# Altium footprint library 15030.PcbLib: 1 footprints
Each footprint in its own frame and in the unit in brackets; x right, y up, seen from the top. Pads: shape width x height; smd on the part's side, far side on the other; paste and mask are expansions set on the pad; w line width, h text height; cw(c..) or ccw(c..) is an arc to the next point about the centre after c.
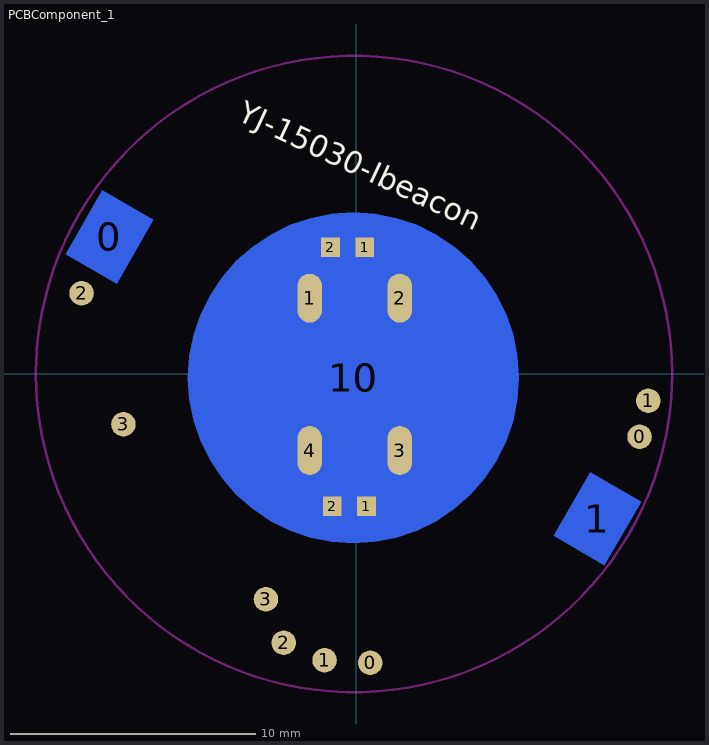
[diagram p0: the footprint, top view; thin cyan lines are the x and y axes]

## PCBComponent_1 [mm]
pads (19):
  rect 2.4x3 smd far side rot 150: 0(-10.074,5.58) 1(9.836,-5.915)
  round 1 smd: 0(0.563,-11.798) 0(11.558,-2.568) 1(-1.297,-11.688) 1(11.917,-1.107) 2(-11.214,3.286) 2(-2.967,-10.978) 3(-9.504,-2.064) 3(-3.687,-9.208)
  oval 1x2 smd: 1(-1.907,3.082) 2(1.773,3.082) 3(1.773,-3.138) 4(-1.907,-3.138)
  rect 0.762x0.813 smd: 1(0.342,5.162) 1(0.412,-5.408) 2(-1.055,5.162) 2(-0.985,-5.408)
  round 13.5 smd far side: 10(-0.123,-0.165)
Top Overlay:
  circle w0.1: c-0.067,-0.028 r1.5
  circle w0.1: c-0.067,-0.028 r1
  lines w0.1: -2.717,-1.678 -2.717,1.622 -1.717,2.622 1.583,2.622 2.583,1.622 2.583,-1.678 1.583,-2.678 -1.717,-2.678 -2.717,-1.678
  lines w0.127: -0.674,4.654 -1.563,4.654 -1.563,5.67 -0.674,5.67 ; -0.604,-5.916 -1.493,-5.916 -1.493,-4.9 -0.604,-4.9 ; -0.039,4.654 0.85,4.654 ; -0.039,5.67 0.85,5.67 ; 0.031,-5.916 0.92,-5.916 ; 0.031,-4.9 0.92,-4.9 ; 0.85,4.654 1.104,4.908 1.104,5.416 0.85,5.67 ; 0.85,4.654 0.85,5.67 ; 0.92,-5.916 1.174,-5.662 1.174,-5.154 0.92,-4.9 ; 0.92,-5.916 0.92,-4.9
  text "YJ-15030-Ibeacon" at -4.907,10.372 h0.9
Keep-Out Layer:
  circle w0.1: c-0.095,-0.011 r12.985
Mechanical 7:
  lines w0.1: -1.057,4.723 -1.057,5.601 ; -0.987,-5.847 -0.987,-4.969 ; -0.957,4.723 -0.957,5.601 ; -0.887,-5.847 -0.887,-4.969 ; 0.243,4.723 0.243,5.601 ; 0.313,-5.847 0.313,-4.969 ; 0.343,4.723 0.343,5.601 ; 0.413,-5.847 0.413,-4.969 ; -1.357,4.723 0.643,4.723 0.643,5.601 -1.357,5.601 -1.357,4.723 ; -1.287,-5.847 0.713,-5.847 0.713,-4.969 -1.287,-4.969 -1.287,-5.847
  text "LED_G" at 0.213,-5.283 h0.3
  text "LED_G" at 0.143,5.287 h0.3
3D body: height 0.6, standoff 0, extent -1.104,-5.808 0.517,-5.008
3D body: height 0.6, standoff 0, extent -1.174,4.762 0.447,5.562
3D body: height 1.5, standoff 1, extent -1.065,-1.028 0.931,0.964
3D body: height 0.2, standoff 0, extent 1.457,-3.584 1.965,-2.314
3D body: height 0.2, standoff 0, extent -2.099,2.258 -1.591,3.528
3D body: height 0.2, standoff 0, extent -2.226,-3.584 -1.591,-2.187
3D body: height 0.2, standoff 0, extent 1.457,2.131 2.092,3.528
3D body: height 1, standoff 0, extent -2.734,-2.695 2.6,2.639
